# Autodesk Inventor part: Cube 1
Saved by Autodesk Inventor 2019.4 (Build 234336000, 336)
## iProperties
Created: 2020-12
Part Number: Cube 1
Material: Generic
Document SubType Name: Modeling
Designer: Administrator
Density: 1 g/cm^3
Appearance: Default
Title: Cube 1
Author: Administrator
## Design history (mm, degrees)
feature "Body1"
body "Solid1"
